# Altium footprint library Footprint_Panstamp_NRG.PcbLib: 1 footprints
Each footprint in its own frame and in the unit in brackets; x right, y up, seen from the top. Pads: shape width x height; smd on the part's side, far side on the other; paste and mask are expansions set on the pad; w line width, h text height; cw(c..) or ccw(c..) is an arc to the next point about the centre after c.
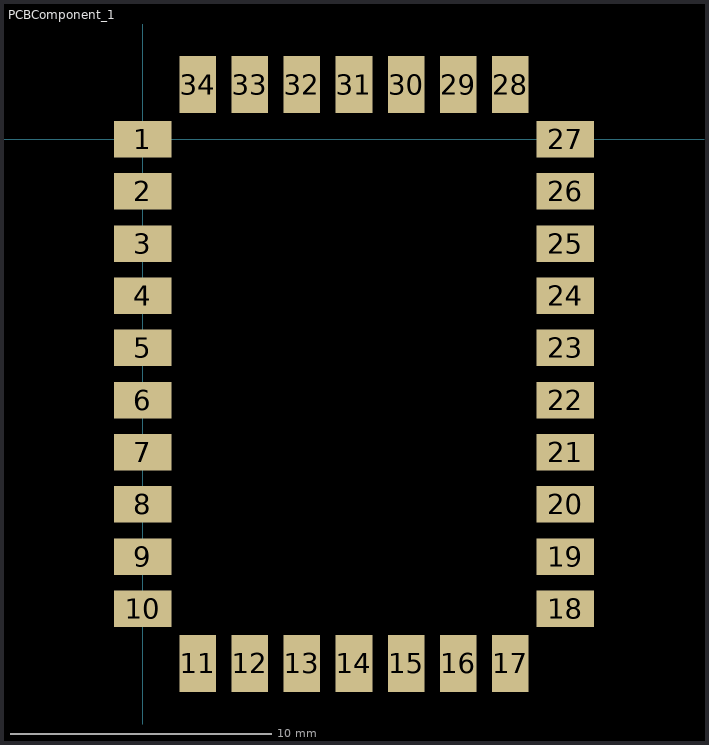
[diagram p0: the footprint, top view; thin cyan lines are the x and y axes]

## PCBComponent_1 [mm]
pads (34):
  rect 2.2x1.4 smd: 1(0,0) 2(0,-1.999) 3(0,-4) 4(0,-6) 5(0,-8) 6(0,-10) 7(0,-12) 8(0,-14) 9(0,-16) 10(0,-18) 18(16.2,-18) 19(16.2,-16) 20(16.2,-14) 21(16.2,-12) 22(16.2,-10) 23(16.2,-8) 24(16.2,-6) 25(16.2,-4) 26(16.2,-2) 27(16.2,0)
  rect 1.4x2.2 smd: 11(2.1,-20.1) 12(4.1,-20.1) 13(6.1,-20.1) 14(8.1,-20.1) 15(10.1,-20.1) 16(12.1,-20.1) 17(14.1,-20.1) 28(14.1,2.1) 29(12.1,2.1) 30(10.1,2.1) 31(8.1,2.1) 32(6.1,2.1) 33(4.1,2.1) 34(2.1,2.1)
